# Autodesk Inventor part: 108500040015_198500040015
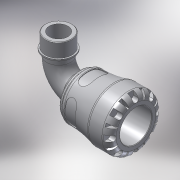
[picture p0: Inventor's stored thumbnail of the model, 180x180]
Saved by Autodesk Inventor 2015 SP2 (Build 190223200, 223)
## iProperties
Created: 2016-12
Part Number: 108500040015_198500040015
Material: PVC-Piping
Description: PLASSON 90° ELBOW WITH THREADED MALE OFFTAKE 40X1.1/2" SERIES 1
Document SubType Name: Modeling
Designer: KIM
Mass: 293.155 g
Surface Area: 513.97 cm^2
Volume: 209.396 cm^3
Density: 1.4 g/cm^3
Appearance: Smooth - White
Author: KIM
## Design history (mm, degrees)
derived "1085.ipt"
feature "Solid1::1085.ipt"
tag "TaggingFeature1"
body "Solid1"
other parameters: "d1" = 29.82, "d8" = 59.5, "d13" = 8, "d14" = 8, "d15" = 0, "d17" = 360 deg, "d19" = 8 deg, "d20" = 0.8, "d21" = 0.8, "d22" = 8 deg, "d24" = 0, "d26" = 360 deg, "d33" = 7, "d43" = 54.6, "d51" = 0.7, "d54" = 14, "d55" = 8.8, "d57" = 15.68, "d58" = 0, "d74" = 0, "d78" = 71, "d82" = 0.8, "d115" = 360 deg, "d207" = 90 deg, "d228" = 11.9, "d247" = 1.4, "d248" = 4.26, "d268" = 32.725, "d269" = 4.26, "d270" = 107, "d276" = 47.803, "d277" = 21, "d278" = 52.5833, "d280" = 23.1, "d281" = 7.17045, "d283" = 43.0227, "d286" = 0, "d287" = 0, "d288" = 33.4621, "d290" = 5.78865, "d292" = 30 deg, "l_" = 71, "A_" = 107, "l_2" = 21, "R_" = 47.803, "d9" = 10, "d289" = 33.4621
